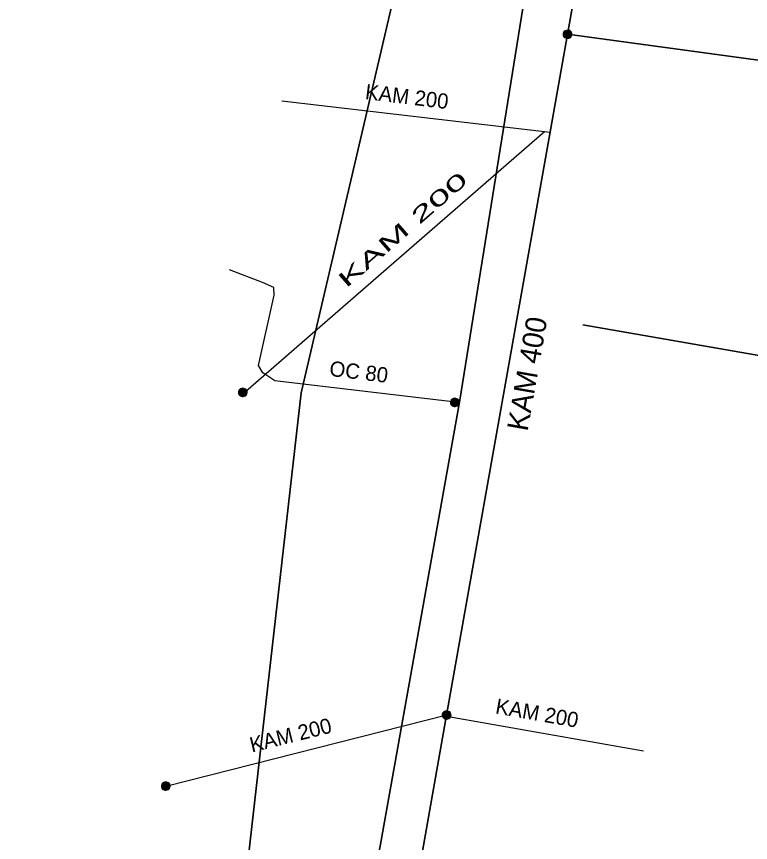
# Model space of a CAD drawing. Extents: x -867121 to -866743, y -1014362 to -1014088.
# Drawn here: x -866806.37 to -866767.71, y -1014225.88 to -1014182.35 of the extents above; entities that cross this region are included whole.
import ezdxf

# ---------------------------------------------------------------- set-up
doc = ezdxf.new("R2010")
doc.units = 0
doc.header["$LTSCALE"] = 0.44
for name, color, linetype, lineweight in [('1', 7, 'Continuous', 35), ('12', 7, 'Continuous', 13), ('21', 7, 'Continuous', 35), ('23', 7, 'Continuous', 25), ('3', 7, 'Continuous', 25), ('32', 7, 'Continuous', 13)]:
    doc.layers.add(name, color=color, linetype=linetype, lineweight=lineweight)

msp = doc.modelspace()

# ---------------------------------------------------------------- linework, layer by layer
at = {"layer": '1'}
msp.add_line((-866753.889, -1014202.559), (-866776.544, -1014198.596), dxfattribs=at)
msp.add_lwpolyline([(-866791.979, -1014256.58), (-866792.57, -1014256.02), (-866792.709, -1014255.69), (-866792.69, -1014255.37), (-866792.5, -1014254.9), (-866792.3, -1014254.24), (-866792, -1014252.89), (-866783.03, -1014202.67), (-866778.1, -1014171.95), (-866772.02, -1014133.72), (-866768.851, -1014115.7)], dxfattribs=at)
at = {"layer": '12'}
for points in [[(-866783.051, -1014202.679), (-866783.057, -1014202.627), (-866783.074, -1014202.577), (-866783.103, -1014202.533), (-866783.14, -1014202.496), (-866783.185, -1014202.469), (-866783.235, -1014202.452), (-866783.288, -1014202.448), (-866783.34, -1014202.455), (-866783.389, -1014202.474), (-866783.432, -1014202.503), (-866783.468, -1014202.542), (-866783.494, -1014202.587), (-866783.51, -1014202.638), (-866783.513, -1014202.69), (-866783.505, -1014202.742), (-866783.485, -1014202.791), (-866783.454, -1014202.834), (-866783.415, -1014202.868), (-866783.369, -1014202.894), (-866783.318, -1014202.908), (-866783.265, -1014202.91), (-866783.214, -1014202.9), (-866783.166, -1014202.879), (-866783.123, -1014202.848), (-866783.089, -1014202.807), (-866783.065, -1014202.761), (-866783.053, -1014202.71)], [(-866783.081, -1014202.679), (-866783.087, -1014202.63), (-866783.104, -1014202.584), (-866783.132, -1014202.544), (-866783.169, -1014202.512), (-866783.213, -1014202.49), (-866783.261, -1014202.479), (-866783.31, -1014202.479), (-866783.357, -1014202.492), (-866783.4, -1014202.516), (-866783.436, -1014202.549), (-866783.463, -1014202.59), (-866783.479, -1014202.637), (-866783.483, -1014202.686), (-866783.476, -1014202.734), (-866783.457, -1014202.779), (-866783.427, -1014202.819), (-866783.389, -1014202.85), (-866783.345, -1014202.87), (-866783.297, -1014202.88), (-866783.248, -1014202.878), (-866783.201, -1014202.863), (-866783.158, -1014202.838), (-866783.124, -1014202.804), (-866783.098, -1014202.762), (-866783.084, -1014202.715)], [(-866783.111, -1014202.679), (-866783.117, -1014202.634), (-866783.134, -1014202.592), (-866783.162, -1014202.557), (-866783.198, -1014202.53), (-866783.24, -1014202.513), (-866783.285, -1014202.508), (-866783.33, -1014202.514), (-866783.371, -1014202.533), (-866783.406, -1014202.561), (-866783.433, -1014202.598), (-866783.449, -1014202.64), (-866783.453, -1014202.685), (-866783.446, -1014202.73), (-866783.427, -1014202.771), (-866783.398, -1014202.805), (-866783.361, -1014202.831), (-866783.318, -1014202.847), (-866783.273, -1014202.85), (-866783.228, -1014202.842), (-866783.188, -1014202.822), (-866783.154, -1014202.793), (-866783.128, -1014202.755), (-866783.114, -1014202.712)], [(-866783.141, -1014202.679), (-866783.146, -1014202.638), (-866783.164, -1014202.601), (-866783.191, -1014202.57), (-866783.226, -1014202.549), (-866783.266, -1014202.538), (-866783.307, -1014202.54), (-866783.346, -1014202.553), (-866783.38, -1014202.577), (-866783.405, -1014202.609), (-866783.42, -1014202.647), (-866783.423, -1014202.688), (-866783.415, -1014202.728), (-866783.395, -1014202.764), (-866783.366, -1014202.793), (-866783.329, -1014202.812), (-866783.289, -1014202.82), (-866783.248, -1014202.816), (-866783.21, -1014202.801), (-866783.178, -1014202.775), (-866783.155, -1014202.741), (-866783.142, -1014202.702)], [(-866783.171, -1014202.679), (-866783.176, -1014202.643), (-866783.194, -1014202.611), (-866783.22, -1014202.586), (-866783.254, -1014202.571), (-866783.29, -1014202.568), (-866783.325, -1014202.576), (-866783.356, -1014202.596), (-866783.379, -1014202.624), (-866783.392, -1014202.658), (-866783.392, -1014202.695), (-866783.381, -1014202.73), (-866783.36, -1014202.759), (-866783.33, -1014202.78), (-866783.295, -1014202.79), (-866783.258, -1014202.788), (-866783.224, -1014202.774), (-866783.197, -1014202.751), (-866783.178, -1014202.719), (-866783.171, -1014202.684)], [(-866783.201, -1014202.679), (-866783.206, -1014202.648), (-866783.223, -1014202.622), (-866783.249, -1014202.605), (-866783.279, -1014202.598), (-866783.31, -1014202.602), (-866783.337, -1014202.619), (-866783.355, -1014202.643), (-866783.363, -1014202.674), (-866783.359, -1014202.704), (-866783.344, -1014202.732), (-866783.32, -1014202.751), (-866783.29, -1014202.76), (-866783.259, -1014202.757), (-866783.231, -1014202.743), (-866783.211, -1014202.719), (-866783.201, -1014202.69)], [(-866783.231, -1014202.679), (-866783.236, -1014202.655), (-866783.253, -1014202.637), (-866783.276, -1014202.628), (-866783.3, -1014202.631), (-866783.321, -1014202.645), (-866783.332, -1014202.667), (-866783.332, -1014202.692), (-866783.32, -1014202.713), (-866783.3, -1014202.727), (-866783.275, -1014202.73), (-866783.252, -1014202.721), (-866783.236, -1014202.703)], [(-866783.261, -1014202.679), (-866783.266, -1014202.664), (-866783.281, -1014202.658), (-866783.296, -1014202.662), (-866783.303, -1014202.676), (-866783.299, -1014202.691), (-866783.286, -1014202.7), (-866783.271, -1014202.697), (-866783.261, -1014202.685)]]:
    msp.add_lwpolyline(points, close=True, dxfattribs=at)
at = {"layer": '21'}
for p, q in [((-866751.815, -1014186.769), (-866777.346, -1014183.28)), ((-866787.796, -1014242.174), (-866783.712, -1014219.159))]:
    msp.add_line(p, q, dxfattribs=at)
for points in [[(-866867.906, -1014313.414), (-866804.195, -1014269.207), (-866794.318, -1014228.125), (-866791.378, -1014202.173), (-866784.04, -1014170.77), (-866768.345, -1014133.735)], [(-866783.712, -1014219.159), (-866777.049, -1014181.604), (-866773.421, -1014161.649)]]:
    msp.add_lwpolyline(points, dxfattribs=at)
at = {"layer": '23'}
for p, q in [((-866792.387, -1014186.789), (-866778.261, -1014188.437)), ((-866794.431, -1014202.205), (-866778.566, -1014188.402)), ((-866798.509, -1014222.908), (-866783.71, -1014219.148)), ((-866773.339, -1014221.07), (-866783.724, -1014219.227))]:
    msp.add_line(p, q, dxfattribs=at)
at = {"layer": '3'}
msp.add_lwpolyline([(-866783.03, -1014202.67), (-866783.25, -1014202.67), (-866792.76, -1014201.55), (-866793.4, -1014201.12), (-866793.63, -1014200.73), (-866792.8, -1014197.03), (-866792.81, -1014196.63), (-866793.41, -1014196.36), (-866795.147, -1014195.693)], dxfattribs=at)
at = {"layer": '32'}
for points in [[(-866777.115, -1014183.28), (-866777.121, -1014183.228), (-866777.138, -1014183.178), (-866777.167, -1014183.134), (-866777.204, -1014183.097), (-866777.249, -1014183.07), (-866777.299, -1014183.053), (-866777.352, -1014183.049), (-866777.404, -1014183.056), (-866777.453, -1014183.075), (-866777.496, -1014183.104), (-866777.532, -1014183.143), (-866777.558, -1014183.188), (-866777.574, -1014183.239), (-866777.577, -1014183.291), (-866777.569, -1014183.343), (-866777.549, -1014183.392), (-866777.518, -1014183.435), (-866777.479, -1014183.469), (-866777.433, -1014183.495), (-866777.382, -1014183.509), (-866777.329, -1014183.511), (-866777.278, -1014183.501), (-866777.23, -1014183.48), (-866777.187, -1014183.449), (-866777.153, -1014183.408), (-866777.129, -1014183.362), (-866777.117, -1014183.311)], [(-866777.145, -1014183.28), (-866777.151, -1014183.231), (-866777.168, -1014183.185), (-866777.196, -1014183.145), (-866777.233, -1014183.113), (-866777.277, -1014183.091), (-866777.325, -1014183.08), (-866777.374, -1014183.08), (-866777.421, -1014183.093), (-866777.464, -1014183.117), (-866777.5, -1014183.15), (-866777.527, -1014183.191), (-866777.543, -1014183.238), (-866777.547, -1014183.287), (-866777.54, -1014183.335), (-866777.521, -1014183.38), (-866777.491, -1014183.42), (-866777.453, -1014183.451), (-866777.409, -1014183.471), (-866777.361, -1014183.481), (-866777.312, -1014183.479), (-866777.265, -1014183.464), (-866777.222, -1014183.439), (-866777.188, -1014183.405), (-866777.162, -1014183.363), (-866777.148, -1014183.316)], [(-866777.175, -1014183.28), (-866777.181, -1014183.235), (-866777.198, -1014183.193), (-866777.226, -1014183.158), (-866777.262, -1014183.131), (-866777.304, -1014183.114), (-866777.349, -1014183.109), (-866777.394, -1014183.115), (-866777.435, -1014183.134), (-866777.47, -1014183.162), (-866777.497, -1014183.199), (-866777.513, -1014183.241), (-866777.517, -1014183.286), (-866777.51, -1014183.331), (-866777.491, -1014183.372), (-866777.462, -1014183.406), (-866777.425, -1014183.432), (-866777.382, -1014183.448), (-866777.337, -1014183.451), (-866777.292, -1014183.443), (-866777.252, -1014183.423), (-866777.218, -1014183.394), (-866777.192, -1014183.356), (-866777.178, -1014183.313)], [(-866777.205, -1014183.28), (-866777.21, -1014183.239), (-866777.228, -1014183.202), (-866777.255, -1014183.171), (-866777.29, -1014183.15), (-866777.33, -1014183.139), (-866777.371, -1014183.141), (-866777.41, -1014183.154), (-866777.444, -1014183.178), (-866777.469, -1014183.21), (-866777.484, -1014183.248), (-866777.487, -1014183.289), (-866777.479, -1014183.329), (-866777.459, -1014183.365), (-866777.43, -1014183.394), (-866777.393, -1014183.413), (-866777.353, -1014183.421), (-866777.312, -1014183.417), (-866777.274, -1014183.402), (-866777.242, -1014183.376), (-866777.219, -1014183.342), (-866777.206, -1014183.303)], [(-866777.235, -1014183.28), (-866777.24, -1014183.244), (-866777.258, -1014183.212), (-866777.284, -1014183.187), (-866777.318, -1014183.172), (-866777.354, -1014183.169), (-866777.389, -1014183.177), (-866777.42, -1014183.197), (-866777.443, -1014183.225), (-866777.456, -1014183.259), (-866777.456, -1014183.296), (-866777.445, -1014183.331), (-866777.424, -1014183.36), (-866777.394, -1014183.381), (-866777.359, -1014183.391), (-866777.322, -1014183.389), (-866777.288, -1014183.375), (-866777.261, -1014183.352), (-866777.242, -1014183.32), (-866777.235, -1014183.285)], [(-866777.265, -1014183.28), (-866777.27, -1014183.249), (-866777.287, -1014183.223), (-866777.313, -1014183.206), (-866777.343, -1014183.199), (-866777.374, -1014183.203), (-866777.401, -1014183.22), (-866777.419, -1014183.244), (-866777.427, -1014183.275), (-866777.423, -1014183.305), (-866777.408, -1014183.333), (-866777.384, -1014183.352), (-866777.354, -1014183.361), (-866777.323, -1014183.358), (-866777.295, -1014183.344), (-866777.275, -1014183.32), (-866777.265, -1014183.291)], [(-866777.295, -1014183.28), (-866777.3, -1014183.256), (-866777.317, -1014183.238), (-866777.34, -1014183.229), (-866777.364, -1014183.232), (-866777.385, -1014183.246), (-866777.396, -1014183.268), (-866777.396, -1014183.293), (-866777.384, -1014183.314), (-866777.364, -1014183.328), (-866777.339, -1014183.331), (-866777.316, -1014183.322), (-866777.3, -1014183.304)], [(-866777.325, -1014183.28), (-866777.33, -1014183.265), (-866777.345, -1014183.259), (-866777.36, -1014183.263), (-866777.367, -1014183.277), (-866777.363, -1014183.292), (-866777.35, -1014183.301), (-866777.335, -1014183.298), (-866777.325, -1014183.286)], [(-866794.218, -1014202.154), (-866794.224, -1014202.102), (-866794.241, -1014202.052), (-866794.27, -1014202.008), (-866794.307, -1014201.971), (-866794.352, -1014201.944), (-866794.402, -1014201.927), (-866794.455, -1014201.923), (-866794.507, -1014201.93), (-866794.556, -1014201.949), (-866794.599, -1014201.978), (-866794.635, -1014202.017), (-866794.661, -1014202.062), (-866794.677, -1014202.113), (-866794.68, -1014202.165), (-866794.672, -1014202.217), (-866794.652, -1014202.266), (-866794.621, -1014202.309), (-866794.582, -1014202.343), (-866794.536, -1014202.369), (-866794.485, -1014202.383), (-866794.432, -1014202.385), (-866794.381, -1014202.375), (-866794.333, -1014202.354), (-866794.29, -1014202.323), (-866794.256, -1014202.282), (-866794.232, -1014202.236), (-866794.22, -1014202.185)], [(-866794.248, -1014202.154), (-866794.254, -1014202.105), (-866794.271, -1014202.059), (-866794.299, -1014202.019), (-866794.336, -1014201.987), (-866794.38, -1014201.965), (-866794.428, -1014201.954), (-866794.477, -1014201.954), (-866794.524, -1014201.967), (-866794.567, -1014201.991), (-866794.603, -1014202.024), (-866794.63, -1014202.065), (-866794.646, -1014202.112), (-866794.65, -1014202.161), (-866794.643, -1014202.209), (-866794.624, -1014202.254), (-866794.594, -1014202.294), (-866794.556, -1014202.325), (-866794.512, -1014202.345), (-866794.464, -1014202.355), (-866794.415, -1014202.353), (-866794.368, -1014202.338), (-866794.325, -1014202.313), (-866794.291, -1014202.279), (-866794.265, -1014202.237), (-866794.251, -1014202.19)], [(-866794.278, -1014202.154), (-866794.284, -1014202.109), (-866794.301, -1014202.067), (-866794.329, -1014202.032), (-866794.365, -1014202.005), (-866794.407, -1014201.988), (-866794.452, -1014201.983), (-866794.497, -1014201.989), (-866794.538, -1014202.008), (-866794.573, -1014202.036), (-866794.6, -1014202.073), (-866794.616, -1014202.115), (-866794.62, -1014202.16), (-866794.613, -1014202.205), (-866794.594, -1014202.246), (-866794.565, -1014202.28), (-866794.528, -1014202.306), (-866794.485, -1014202.322), (-866794.44, -1014202.325), (-866794.395, -1014202.317), (-866794.355, -1014202.297), (-866794.321, -1014202.268), (-866794.295, -1014202.23), (-866794.281, -1014202.187)], [(-866794.308, -1014202.154), (-866794.313, -1014202.113), (-866794.331, -1014202.076), (-866794.358, -1014202.045), (-866794.393, -1014202.024), (-866794.433, -1014202.013), (-866794.474, -1014202.015), (-866794.513, -1014202.028), (-866794.547, -1014202.052), (-866794.572, -1014202.084), (-866794.587, -1014202.122), (-866794.59, -1014202.163), (-866794.582, -1014202.203), (-866794.562, -1014202.239), (-866794.533, -1014202.268), (-866794.496, -1014202.287), (-866794.456, -1014202.295), (-866794.415, -1014202.291), (-866794.377, -1014202.276), (-866794.345, -1014202.25), (-866794.322, -1014202.216), (-866794.309, -1014202.177)], [(-866794.338, -1014202.154), (-866794.343, -1014202.118), (-866794.361, -1014202.086), (-866794.387, -1014202.061), (-866794.421, -1014202.046), (-866794.457, -1014202.043), (-866794.492, -1014202.051), (-866794.523, -1014202.071), (-866794.546, -1014202.099), (-866794.559, -1014202.133), (-866794.559, -1014202.17), (-866794.548, -1014202.205), (-866794.527, -1014202.234), (-866794.497, -1014202.255), (-866794.462, -1014202.265), (-866794.425, -1014202.263), (-866794.391, -1014202.249), (-866794.364, -1014202.226), (-866794.345, -1014202.194), (-866794.338, -1014202.159)], [(-866794.368, -1014202.154), (-866794.373, -1014202.123), (-866794.39, -1014202.097), (-866794.416, -1014202.08), (-866794.446, -1014202.073), (-866794.477, -1014202.077), (-866794.504, -1014202.094), (-866794.522, -1014202.118), (-866794.53, -1014202.149), (-866794.526, -1014202.179), (-866794.511, -1014202.207), (-866794.487, -1014202.226), (-866794.457, -1014202.235), (-866794.426, -1014202.232), (-866794.398, -1014202.218), (-866794.378, -1014202.194), (-866794.368, -1014202.165)], [(-866794.398, -1014202.154), (-866794.403, -1014202.13), (-866794.42, -1014202.112), (-866794.443, -1014202.103), (-866794.467, -1014202.106), (-866794.488, -1014202.12), (-866794.499, -1014202.142), (-866794.499, -1014202.167), (-866794.487, -1014202.188), (-866794.467, -1014202.202), (-866794.442, -1014202.205), (-866794.419, -1014202.196), (-866794.403, -1014202.178)], [(-866794.428, -1014202.154), (-866794.433, -1014202.139), (-866794.448, -1014202.133), (-866794.463, -1014202.137), (-866794.47, -1014202.151), (-866794.466, -1014202.166), (-866794.453, -1014202.175), (-866794.438, -1014202.172), (-866794.428, -1014202.16)], [(-866783.481, -1014219.159), (-866783.487, -1014219.107), (-866783.504, -1014219.057), (-866783.533, -1014219.013), (-866783.57, -1014218.976), (-866783.615, -1014218.949), (-866783.665, -1014218.932), (-866783.718, -1014218.928), (-866783.77, -1014218.935), (-866783.819, -1014218.954), (-866783.862, -1014218.983), (-866783.898, -1014219.022), (-866783.924, -1014219.067), (-866783.94, -1014219.118), (-866783.943, -1014219.17), (-866783.935, -1014219.222), (-866783.915, -1014219.271), (-866783.884, -1014219.314), (-866783.845, -1014219.348), (-866783.799, -1014219.374), (-866783.748, -1014219.388), (-866783.695, -1014219.39), (-866783.644, -1014219.38), (-866783.596, -1014219.359), (-866783.553, -1014219.328), (-866783.519, -1014219.287), (-866783.495, -1014219.241), (-866783.483, -1014219.19)], [(-866783.511, -1014219.159), (-866783.517, -1014219.11), (-866783.534, -1014219.064), (-866783.562, -1014219.024), (-866783.599, -1014218.992), (-866783.643, -1014218.97), (-866783.691, -1014218.959), (-866783.74, -1014218.959), (-866783.787, -1014218.972), (-866783.83, -1014218.996), (-866783.866, -1014219.029), (-866783.893, -1014219.07), (-866783.909, -1014219.117), (-866783.913, -1014219.166), (-866783.906, -1014219.214), (-866783.887, -1014219.259), (-866783.857, -1014219.299), (-866783.819, -1014219.33), (-866783.775, -1014219.35), (-866783.727, -1014219.36), (-866783.678, -1014219.358), (-866783.631, -1014219.343), (-866783.588, -1014219.318), (-866783.554, -1014219.284), (-866783.528, -1014219.242), (-866783.514, -1014219.195)], [(-866783.541, -1014219.159), (-866783.547, -1014219.114), (-866783.564, -1014219.072), (-866783.592, -1014219.037), (-866783.628, -1014219.01), (-866783.67, -1014218.993), (-866783.715, -1014218.988), (-866783.76, -1014218.994), (-866783.801, -1014219.013), (-866783.836, -1014219.041), (-866783.863, -1014219.078), (-866783.879, -1014219.12), (-866783.883, -1014219.165), (-866783.876, -1014219.21), (-866783.857, -1014219.251), (-866783.828, -1014219.285), (-866783.791, -1014219.311), (-866783.748, -1014219.327), (-866783.703, -1014219.33), (-866783.658, -1014219.322), (-866783.618, -1014219.302), (-866783.584, -1014219.273), (-866783.558, -1014219.235), (-866783.544, -1014219.192)], [(-866783.571, -1014219.159), (-866783.576, -1014219.118), (-866783.594, -1014219.081), (-866783.621, -1014219.05), (-866783.656, -1014219.029), (-866783.696, -1014219.018), (-866783.737, -1014219.02), (-866783.776, -1014219.033), (-866783.81, -1014219.057), (-866783.835, -1014219.089), (-866783.85, -1014219.127), (-866783.853, -1014219.168), (-866783.845, -1014219.208), (-866783.825, -1014219.244), (-866783.796, -1014219.273), (-866783.759, -1014219.292), (-866783.719, -1014219.3), (-866783.678, -1014219.296), (-866783.64, -1014219.281), (-866783.608, -1014219.255), (-866783.585, -1014219.221), (-866783.572, -1014219.182)], [(-866783.601, -1014219.159), (-866783.606, -1014219.123), (-866783.624, -1014219.091), (-866783.65, -1014219.066), (-866783.684, -1014219.051), (-866783.72, -1014219.048), (-866783.755, -1014219.056), (-866783.786, -1014219.076), (-866783.809, -1014219.104), (-866783.822, -1014219.138), (-866783.822, -1014219.175), (-866783.811, -1014219.21), (-866783.79, -1014219.239), (-866783.76, -1014219.26), (-866783.725, -1014219.27), (-866783.688, -1014219.268), (-866783.654, -1014219.254), (-866783.627, -1014219.231), (-866783.608, -1014219.199), (-866783.601, -1014219.164)], [(-866783.631, -1014219.159), (-866783.636, -1014219.128), (-866783.653, -1014219.102), (-866783.679, -1014219.085), (-866783.709, -1014219.078), (-866783.74, -1014219.082), (-866783.767, -1014219.099), (-866783.785, -1014219.123), (-866783.793, -1014219.154), (-866783.789, -1014219.184), (-866783.774, -1014219.212), (-866783.75, -1014219.231), (-866783.72, -1014219.24), (-866783.689, -1014219.237), (-866783.661, -1014219.223), (-866783.641, -1014219.199), (-866783.631, -1014219.17)], [(-866783.661, -1014219.159), (-866783.666, -1014219.135), (-866783.683, -1014219.117), (-866783.706, -1014219.108), (-866783.73, -1014219.111), (-866783.751, -1014219.125), (-866783.762, -1014219.147), (-866783.762, -1014219.172), (-866783.75, -1014219.193), (-866783.73, -1014219.207), (-866783.705, -1014219.21), (-866783.682, -1014219.201), (-866783.666, -1014219.183)], [(-866783.691, -1014219.159), (-866783.696, -1014219.144), (-866783.711, -1014219.138), (-866783.726, -1014219.142), (-866783.733, -1014219.156), (-866783.729, -1014219.171), (-866783.716, -1014219.18), (-866783.701, -1014219.177), (-866783.691, -1014219.165)], [(-866798.272, -1014222.903), (-866798.279, -1014222.851), (-866798.296, -1014222.801), (-866798.325, -1014222.757), (-866798.362, -1014222.72), (-866798.407, -1014222.693), (-866798.456, -1014222.676), (-866798.51, -1014222.672), (-866798.561, -1014222.679), (-866798.61, -1014222.698), (-866798.654, -1014222.727), (-866798.69, -1014222.766), (-866798.716, -1014222.811), (-866798.732, -1014222.862), (-866798.735, -1014222.914), (-866798.727, -1014222.966), (-866798.706, -1014223.015), (-866798.676, -1014223.058), (-866798.637, -1014223.092), (-866798.591, -1014223.118), (-866798.539, -1014223.132), (-866798.487, -1014223.134), (-866798.436, -1014223.124), (-866798.387, -1014223.103), (-866798.345, -1014223.072), (-866798.311, -1014223.031), (-866798.287, -1014222.985), (-866798.274, -1014222.934)], [(-866798.303, -1014222.903), (-866798.309, -1014222.854), (-866798.326, -1014222.808), (-866798.353, -1014222.768), (-866798.391, -1014222.736), (-866798.434, -1014222.714), (-866798.483, -1014222.703), (-866798.532, -1014222.703), (-866798.578, -1014222.716), (-866798.622, -1014222.74), (-866798.657, -1014222.773), (-866798.684, -1014222.814), (-866798.701, -1014222.861), (-866798.705, -1014222.91), (-866798.698, -1014222.958), (-866798.679, -1014223.003), (-866798.649, -1014223.043), (-866798.61, -1014223.074), (-866798.566, -1014223.094), (-866798.519, -1014223.104), (-866798.47, -1014223.102), (-866798.423, -1014223.087), (-866798.38, -1014223.062), (-866798.345, -1014223.028), (-866798.32, -1014222.986), (-866798.306, -1014222.939)], [(-866798.333, -1014222.903), (-866798.338, -1014222.858), (-866798.355, -1014222.816), (-866798.384, -1014222.781), (-866798.419, -1014222.754), (-866798.462, -1014222.737), (-866798.507, -1014222.732), (-866798.551, -1014222.738), (-866798.593, -1014222.757), (-866798.627, -1014222.785), (-866798.654, -1014222.822), (-866798.671, -1014222.864), (-866798.674, -1014222.909), (-866798.668, -1014222.954), (-866798.649, -1014222.995), (-866798.62, -1014223.029), (-866798.583, -1014223.055), (-866798.539, -1014223.071), (-866798.495, -1014223.074), (-866798.45, -1014223.066), (-866798.409, -1014223.046), (-866798.375, -1014223.017), (-866798.35, -1014222.979), (-866798.336, -1014222.936)], [(-866798.363, -1014222.903), (-866798.367, -1014222.862), (-866798.386, -1014222.825), (-866798.413, -1014222.794), (-866798.448, -1014222.773), (-866798.488, -1014222.762), (-866798.529, -1014222.764), (-866798.568, -1014222.777), (-866798.602, -1014222.801), (-866798.627, -1014222.833), (-866798.642, -1014222.871), (-866798.644, -1014222.912), (-866798.637, -1014222.952), (-866798.617, -1014222.988), (-866798.588, -1014223.017), (-866798.551, -1014223.036), (-866798.511, -1014223.044), (-866798.47, -1014223.04), (-866798.431, -1014223.025), (-866798.399, -1014222.999), (-866798.377, -1014222.965), (-866798.364, -1014222.926)], [(-866798.392, -1014222.903), (-866798.397, -1014222.867), (-866798.416, -1014222.835), (-866798.441, -1014222.81), (-866798.475, -1014222.795), (-866798.512, -1014222.792), (-866798.546, -1014222.8), (-866798.578, -1014222.82), (-866798.6, -1014222.848), (-866798.614, -1014222.882), (-866798.614, -1014222.919), (-866798.603, -1014222.954), (-866798.581, -1014222.983), (-866798.551, -1014223.004), (-866798.517, -1014223.014), (-866798.48, -1014223.012), (-866798.446, -1014222.998), (-866798.419, -1014222.975), (-866798.399, -1014222.943), (-866798.392, -1014222.908)], [(-866798.423, -1014222.903), (-866798.428, -1014222.872), (-866798.445, -1014222.846), (-866798.47, -1014222.829), (-866798.5, -1014222.822), (-866798.532, -1014222.826), (-866798.559, -1014222.843), (-866798.576, -1014222.867), (-866798.585, -1014222.898), (-866798.581, -1014222.928), (-866798.566, -1014222.956), (-866798.541, -1014222.975), (-866798.512, -1014222.984), (-866798.48, -1014222.981), (-866798.453, -1014222.967), (-866798.433, -1014222.943), (-866798.423, -1014222.914)], [(-866798.453, -1014222.903), (-866798.458, -1014222.879), (-866798.475, -1014222.861), (-866798.497, -1014222.852), (-866798.522, -1014222.855), (-866798.543, -1014222.869), (-866798.554, -1014222.891), (-866798.554, -1014222.916), (-866798.541, -1014222.937), (-866798.522, -1014222.951), (-866798.497, -1014222.954), (-866798.473, -1014222.945), (-866798.458, -1014222.927)], [(-866798.483, -1014222.903), (-866798.488, -1014222.888), (-866798.502, -1014222.882), (-866798.517, -1014222.886), (-866798.524, -1014222.9), (-866798.521, -1014222.915), (-866798.507, -1014222.924), (-866798.492, -1014222.921), (-866798.483, -1014222.909)]]:
    msp.add_lwpolyline(points, close=True, dxfattribs=at)

# ---------------------------------------------------------------- texts
at = {"layer": '1'}
for s, height, rotation, p in [('KAM 200 ', 0.8, 353, (-866788.036, -1014186.692)), ('KAM 400 ', 1.1, 80, (-866779.453, -1014204.244)), ('OC 80 ', 0.8, 353, (-866789.921, -1014201.279)), ('KAM 200 ', 0.8, 350, (-866781.183, -1014219.068)), ('KAM 200 ', 0.8, 14, (-866793.971, -1014221.136))]:
    msp.add_text(s, height=height, rotation=rotation, dxfattribs=at).set_placement(p)
at = {"layer": '1', "width": 1.95}
msp.add_text('KAM 200 ', height=0.8, rotation=41, dxfattribs=at).set_placement((-866789.004, -1014196.688))

doc.saveas('drawing.dxf')
